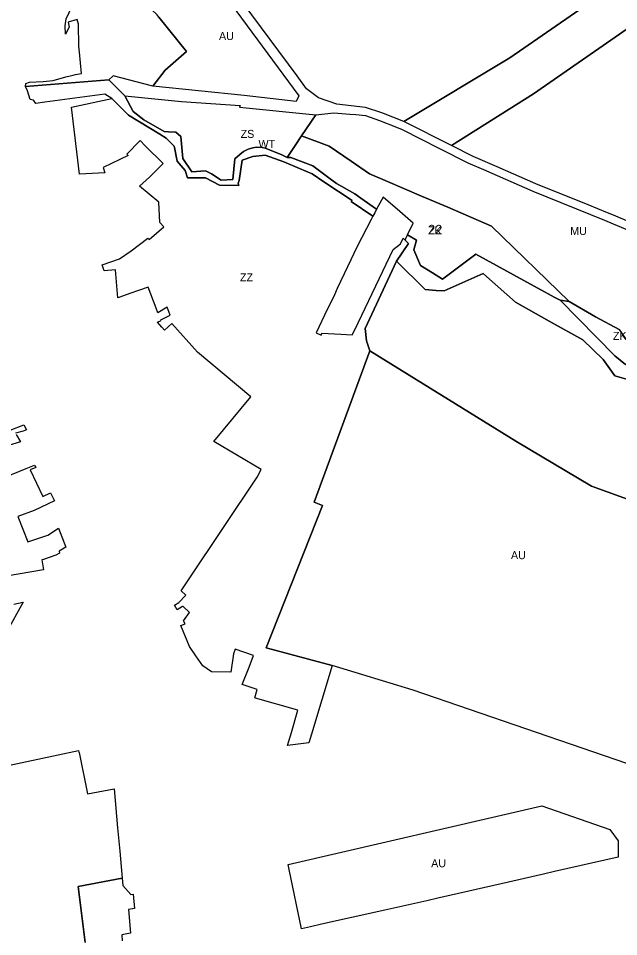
# Model space of a CAD drawing. Extents: x -522079 to -518833, y -1142398 to -1139961.
# Drawn here: x -520390 to -520015, y -1141329 to -1140756 of the extents above; entities that cross this region are included whole.
import ezdxf

# ---------------------------------------------------------------- set-up
doc = ezdxf.new("R2010")
doc.units = 0
for name, color, linetype in [('90640013', 7, 'Continuous'), ('90660013', 7, 'Continuous'), ('90670013', 7, 'Continuous'), ('90710013', 7, 'Continuous'), ('90710023', 7, 'Continuous'), ('90750013', 7, 'Continuous'), ('90830013', 7, 'Continuous'), ('ID_navrh', 7, 'Continuous')]:
    doc.layers.add(name, color=color, linetype=linetype)

msp = doc.modelspace()

# ---------------------------------------------------------------- linework, layer by layer
at = {"layer": '90640013'}
msp.add_lwpolyline([(-520333.88, -1140793.93), (-520323.97, -1140803.87), (-520318.65, -1140813.75), (-520312.05, -1140818.87), (-520299.28, -1140826.27), (-520296.51, -1140826.43), (-520292.1, -1140826.69), (-520288.8, -1140829.33), (-520287.73, -1140843.06), (-520282.03, -1140851.48), (-520273.45, -1140850.74), (-520269.7, -1140852.75), (-520263.6, -1140856.56), (-520256.4, -1140856.26), (-520255.19, -1140843.37), (-520252.14, -1140840.56), (-520249.76, -1140838.76), (-520246.91, -1140837.31), (-520243.86, -1140836.42), (-520241.55, -1140836.1), (-520237.99, -1140836.24), (-520236.14, -1140836.59), (-520226.15, -1140840.68), (-520222.55, -1140842.43), (-520220.12, -1140842.45), (-520206.43, -1140847.59), (-520196.46, -1140855.08), (-520191.59, -1140858.73), (-520180.27, -1140865.22), (-520176.48, -1140867.88), (-520166.62, -1140874.78), (-520167.79, -1140876.9), (-520168.95, -1140879.03), (-520182.55, -1140869.96), (-520181.95, -1140869.32), (-520199.46, -1140857.65), (-520206.95, -1140852.59), (-520214.8, -1140849.22), (-520224.47, -1140845.06), (-520236.26, -1140840.92), (-520243.98, -1140841.86), (-520250.57, -1140844.07), (-520252.48, -1140856.73), (-520253.04, -1140858.58), (-520252.57, -1140859.91), (-520264.75, -1140859.75), (-520273.49, -1140855.19), (-520284.67, -1140855.24), (-520286.12, -1140850.49), (-520291.11, -1140844.75), (-520292.87, -1140836.23), (-520293.05, -1140835.38), (-520298.02, -1140830.46), (-520302.1, -1140827.97), (-520321.54, -1140816.1), (-520332, -1140805.6), (-520331.98, -1140805.6), (-520336.41, -1140802.99), (-520373.88, -1140807.82), (-520379.43, -1140808.81), (-520380.85, -1140806.63), (-520383.09, -1140806.25), (-520384.61, -1140800.83), (-520385.85, -1140798.14)], close=True, dxfattribs=at)
msp.add_lwpolyline([(-520003.11, -1140982.94), (-520017.73, -1140978.78), (-520025.01, -1140968.52), (-520037.81, -1140956.24), (-520058.84, -1140944.58), (-520079.83, -1140932.73), (-520097.88, -1140916.76), (-520100.12, -1140914.78), (-520124.49, -1140925.8), (-520129.31, -1140925.55), (-520136.24, -1140924.81), (-520154.18, -1140907.23), (-520146.75, -1140896.12), (-520148.74, -1140894), (-520148.27, -1140892.97), (-520147.23, -1140890.72), (-520141.61, -1140894.1), (-520143.26, -1140900.05), (-520139.09, -1140909.85), (-520131.65, -1140914.52), (-520125.39, -1140918.45), (-520104.55, -1140902.75), (-520061.67, -1140926.36), (-520059.41, -1140927.64), (-520055.67, -1140929.56), (-520051.93, -1140931.48), (-520017.69, -1140966.19), (-520011.16, -1140971.75)], dxfattribs=at)
at = {"layer": '90660013'}
msp.add_lwpolyline([(-520213.5, -1140828.96), (-520217.49, -1140834.9), (-520222.55, -1140842.43), (-520226.15, -1140840.68), (-520236.14, -1140836.59), (-520237.99, -1140836.24), (-520241.55, -1140836.1), (-520243.86, -1140836.42), (-520246.91, -1140837.31), (-520249.76, -1140838.76), (-520252.14, -1140840.56), (-520255.19, -1140843.37), (-520256.4, -1140856.26), (-520263.6, -1140856.56), (-520269.7, -1140852.75), (-520273.45, -1140850.74), (-520282.03, -1140851.48), (-520287.73, -1140843.06), (-520288.8, -1140829.33), (-520292.1, -1140826.69), (-520296.51, -1140826.43), (-520299.28, -1140826.27), (-520312.05, -1140818.87), (-520318.65, -1140813.75), (-520323.97, -1140803.87), (-520288.38, -1140807.41), (-520251.92, -1140810), (-520252.34, -1140811), (-520204.62, -1140815.75)], close=True, dxfattribs=at)
at = {"layer": '90670013'}
for points in [[(-520302.54, -1140754.92), (-520285.25, -1140776.21), (-520298.77, -1140787.91), (-520306.3, -1140797.86), (-520331.09, -1140791.46), (-520333.88, -1140793.93), (-520385.85, -1140798.14), (-520385.62, -1140796.31), (-520383.53, -1140795.4), (-520374.96, -1140794.94), (-520368.73, -1140794.29), (-520360.72, -1140792.17), (-520356.2, -1140791.03), (-520354.62, -1140790.65), (-520350.89, -1140789.92), (-520352.17, -1140776.77), (-520352.71, -1140773.02), (-520352.78, -1140759.2), (-520353.64, -1140756.21), (-520359.31, -1140757.88), (-520358.59, -1140760.98), (-520361.04, -1140765.41), (-520361.11, -1140760.14), (-520360.42, -1140755.8), (-520354.98, -1140743.86)], [(-520395.43, -1141012.8), (-520386.94, -1141009.33), (-520385.38, -1141012.44), (-520387.31, -1141013.36), (-520392.22, -1141014.66)], [(-520391.74, -1141015.46), (-520389.08, -1141019.93), (-520401.32, -1141023.68)], [(-520399.24, -1141042.3), (-520385.48, -1141036.63), (-520380.26, -1141034.58), (-520380, -1141035.01), (-520379.56, -1141036.01), (-520382.96, -1141037.48), (-520375, -1141054.13), (-520370.31, -1141051.82), (-520367.77, -1141056.92), (-520380.42, -1141062.83), (-520390.79, -1141066.51), (-520384.48, -1141082.4), (-520371.97, -1141078.27), (-520365.3, -1141073.88), (-520360.71, -1141085.77), (-520364.98, -1141088.31), (-520364.74, -1141089.55), (-520366.94, -1141090.81), (-520374.62, -1141093.47), (-520375.66, -1141093.7), (-520374.68, -1141099.98), (-520397.79, -1141103.97)], [(-520393.3, -1141121.36), (-520387.46, -1141120.02), (-520397.97, -1141139.24)], [(-520348.74, -1141332.58), (-520353.1, -1141297.63), (-520325.5, -1141292.44), (-520325.09, -1141296.95), (-520320.11, -1141302.71), (-520318.74, -1141302.49), (-520317.9, -1141311.37), (-520321.67, -1141312.05), (-520320.3, -1141326.77), (-520325.78, -1141327.89), (-520325.53, -1141331.62)]]:
    msp.add_lwpolyline(points, dxfattribs=at)
msp.add_lwpolyline([(-520209, -1141207.86), (-520222.29, -1141209.66), (-520219.73, -1141201.41), (-520215.84, -1141187.57), (-520242.23, -1141179.94), (-520242.77, -1141179.78), (-520241.26, -1141174.54), (-520250.48, -1141171.53), (-520246.26, -1141160.66), (-520243.41, -1141153.37), (-520254.95, -1141149.39), (-520256.03, -1141152.27), (-520257.71, -1141163.82), (-520269.77, -1141163.56), (-520275.19, -1141159.91), (-520279.46, -1141153.62), (-520283.41, -1141147.79), (-520288.84, -1141134.57), (-520286.17, -1141133.59), (-520287.28, -1141131.69), (-520283.49, -1141126.48), (-520287.59, -1141122.55), (-520287.92, -1141122.9), (-520291.23, -1141124.89), (-520292.95, -1141121.95), (-520290.1, -1141120.29), (-520285.76, -1141115.8), (-520288.75, -1141112.92), (-520283.75, -1141105.56), (-520241.17, -1141042.05), (-520238.67, -1141037.33), (-520268.23, -1141019.69), (-520245.17, -1140991.88), (-520278.46, -1140964.1), (-520294.61, -1140946.2), (-520299.04, -1140950.24), (-520300.74, -1140948.36), (-520303.52, -1140945.28), (-520301.23, -1140944.23), (-520301.37, -1140943.86), (-520295.5, -1140940.8), (-520297.35, -1140935.94), (-520303.17, -1140939.4), (-520304.25, -1140936.55), (-520309.29, -1140923.33), (-520320.68, -1140927.43), (-520327.1, -1140929.75), (-520328.35, -1140930.16), (-520329.64, -1140912.5), (-520336.89, -1140913.16), (-520338.02, -1140909.41), (-520327.22, -1140905.73), (-520319.94, -1140900.63), (-520309.51, -1140892.73), (-520308.71, -1140893.63), (-520299.57, -1140885.75), (-520301.99, -1140882.96), (-520302.58, -1140870.36), (-520314.68, -1140860.36), (-520308.39, -1140854.65), (-520299.93, -1140846.14), (-520311.07, -1140835.07), (-520314.26, -1140831.9), (-520322.72, -1140840.41), (-520321.89, -1140841.23), (-520337.42, -1140848.62), (-520336.35, -1140852.04), (-520352.17, -1140852.78), (-520357.19, -1140810.98), (-520332, -1140805.6), (-520321.54, -1140816.1), (-520302.1, -1140827.97), (-520298.02, -1140830.46), (-520293.05, -1140835.38), (-520292.87, -1140836.23), (-520291.11, -1140844.75), (-520286.12, -1140850.49), (-520284.67, -1140855.24), (-520273.49, -1140855.19), (-520264.75, -1140859.75), (-520252.57, -1140859.91), (-520253.04, -1140858.58), (-520252.48, -1140856.73), (-520250.57, -1140844.07), (-520243.98, -1140841.86), (-520236.26, -1140840.92), (-520224.47, -1140845.06), (-520214.8, -1140849.22), (-520206.95, -1140852.59), (-520199.46, -1140857.65), (-520181.95, -1140869.32), (-520182.55, -1140869.96), (-520168.95, -1140879.03), (-520170.08, -1140881.1), (-520178.74, -1140898.05), (-520184.7, -1140910.65), (-520191.17, -1140924.29), (-520193, -1140928.16), (-520196.08, -1140934.67), (-520197.39, -1140937.44), (-520204.29, -1140951.99), (-520201.3, -1140953.32), (-520201.27, -1140953.32), (-520200.79, -1140952.24), (-520189.01, -1140952.86), (-520181.77, -1140953.24), (-520180.26, -1140950.09), (-520156.19, -1140899.86), (-520151.68, -1140896.26), (-520149.94, -1140892.73), (-520148.74, -1140894), (-520146.75, -1140896.12), (-520154.18, -1140907.23), (-520173.77, -1140949.3), (-520172.97, -1140956.99), (-520170.88, -1140963.13), (-520205.51, -1141057.7), (-520200.4, -1141059.73), (-520235.62, -1141148.58), (-520194.38, -1141159.65), (-520207.36, -1141202.47)], close=True, dxfattribs=at)
at = {"layer": '90710013'}
msp.add_lwpolyline([(-520010.06, -1140762.16), (-520068.52, -1140802.68), (-520119.77, -1140834.99), (-520149.6, -1140820.02), (-520083.41, -1140780.15), (-520025.44, -1140739.97)], dxfattribs=at)
msp.add_lwpolyline([(-520015.17, -1140949.95), (-520009.84, -1140957.29), (-520002.28, -1140962.91), (-519999.3, -1140964.63), (-519986.94, -1140971.3), (-519974.08, -1140974.02), (-519965.47, -1140973.69), (-519979.37, -1140981.19), (-520011.16, -1140971.75), (-520017.69, -1140966.19), (-520051.93, -1140931.48), (-520046.33, -1140932.29), (-520029.76, -1140941.98)], close=True, dxfattribs=at)
at = {"layer": '90710023'}
msp.add_lwpolyline([(-520213.5, -1140828.96), (-520196.23, -1140835.45), (-520182.58, -1140844.72), (-520170.98, -1140852.6), (-520159.88, -1140857.36), (-520138.6, -1140866.49), (-520122.13, -1140873.55), (-520094.9, -1140885.23), (-520046.33, -1140932.29), (-520051.93, -1140931.48), (-520055.67, -1140929.56), (-520059.41, -1140927.64), (-520061.67, -1140926.36), (-520104.55, -1140902.75), (-520125.39, -1140918.45), (-520131.65, -1140914.52), (-520139.09, -1140909.85), (-520143.26, -1140900.05), (-520141.61, -1140894.1), (-520147.23, -1140890.72), (-520143.83, -1140883.35), (-520152.09, -1140876.15), (-520162.5, -1140867.24), (-520166.62, -1140874.78), (-520176.48, -1140867.88), (-520180.27, -1140865.22), (-520191.59, -1140858.73), (-520196.46, -1140855.08), (-520206.43, -1140847.59), (-520220.12, -1140842.45), (-520222.55, -1140842.43), (-520217.49, -1140834.9)], close=True, dxfattribs=at)
at = {"layer": '90750013'}
for points in [[(-520306.3, -1140797.86), (-520298.77, -1140787.91), (-520285.25, -1140776.21), (-520302.54, -1140754.92), (-520303.74, -1140753.44), (-520314.83, -1140742.62), (-520298.98, -1140728.74), (-520284.03, -1140723.41), (-520276.72, -1140720.19), (-520215.27, -1140803.99), (-520216.9, -1140807.42), (-520249.32, -1140803.75)], [(-520194.38, -1141159.65), (-520235.62, -1141148.58), (-520200.4, -1141059.73), (-520205.51, -1141057.7), (-520170.88, -1140963.13), (-520079.53, -1141019.58), (-520032.33, -1141047.7), (-519951.21, -1141077.01), (-519948.1, -1141084.44), (-519980.55, -1141165.39), (-520002.99, -1141223.35), (-520143.75, -1141175.06)], [(-520128.28, -1141304.98), (-520135.15, -1141306.52), (-520161.5, -1141312.42), (-520200.99, -1141321.26), (-520207.86, -1141322.8), (-520213.54, -1141324.07), (-520221.2, -1141287.03), (-520221.83, -1141283.92), (-520063.43, -1141247.22), (-520020.82, -1141261.97), (-520015.63, -1141269.2), (-520015.8, -1141279.3), (-520055.42, -1141288.36), (-520062.28, -1141289.92), (-520088.69, -1141295.96), (-520120.09, -1141303.14)]]:
    msp.add_lwpolyline(points, close=True, dxfattribs=at)
for points in [[(-520025.44, -1140739.97), (-520083.41, -1140780.15), (-520149.6, -1140820.02), (-520163.23, -1140814.61), (-520173.51, -1140811.18), (-520191.48, -1140809.25), (-520202.97, -1140805.12), (-520210.31, -1140799.64), (-520216.26, -1140791.5), (-520249.86, -1140745.99)], [(-519997.49, -1140887.4), (-520018.57, -1140878.52), (-520022.3, -1140876.95), (-520034.41, -1140872.06), (-520067.09, -1140858.86), (-520091.34, -1140848.28), (-520106.23, -1140841.79), (-520119.77, -1140834.99), (-520068.52, -1140802.68), (-520010.06, -1140762.16)], [(-520400.61, -1141222.82), (-520352.78, -1141212.63), (-520352.51, -1141213.97), (-520352.46, -1141213.96), (-520347.19, -1141239.81), (-520330.62, -1141236.74), (-520328.39, -1141261.02), (-520327.05, -1141275.53), (-520325.5, -1141292.44), (-520353.1, -1141297.63), (-520348.74, -1141332.58)]]:
    msp.add_lwpolyline(points, dxfattribs=at)
at = {"layer": '90830013'}
for points in [[(-520015.17, -1140949.95), (-520029.76, -1140941.98), (-520046.33, -1140932.29), (-520094.9, -1140885.23), (-520122.13, -1140873.55), (-520138.6, -1140866.49), (-520159.88, -1140857.36), (-520170.98, -1140852.6), (-520182.58, -1140844.72), (-520196.23, -1140835.45), (-520213.5, -1140828.96), (-520204.62, -1140815.75), (-520193.39, -1140814.61), (-520183.32, -1140815.4), (-520179.62, -1140815.67), (-520173.51, -1140816.17), (-520164.79, -1140819.27), (-520154.23, -1140823.56), (-520150.53, -1140825.07), (-520127.38, -1140836.75), (-520109.6, -1140845.72), (-520099.84, -1140850.03), (-520069.02, -1140863.47), (-520024.21, -1140881.57), (-520022.73, -1140882.19), (-519999.48, -1140892)], [(-519951.21, -1141077.01), (-520032.33, -1141047.7), (-520079.53, -1141019.58), (-520170.88, -1140963.13), (-520172.97, -1140956.99), (-520173.77, -1140949.3), (-520154.18, -1140907.23), (-520136.24, -1140924.81), (-520129.31, -1140925.55), (-520124.49, -1140925.8), (-520100.12, -1140914.78), (-520097.88, -1140916.76), (-520079.83, -1140932.73), (-520058.84, -1140944.58), (-520037.81, -1140956.24), (-520025.01, -1140968.52), (-520017.73, -1140978.78), (-520003.11, -1140982.94)]]:
    msp.add_lwpolyline(points, dxfattribs=at)

# ---------------------------------------------------------------- texts
at = {"layer": '90640013'}
msp.add_text('WT', height=5, rotation=0, dxfattribs=at).set_placement((-520240.394, -1140836.48))
at = {"layer": '90660013'}
msp.add_text('ZS', height=5, rotation=360, dxfattribs=at).set_placement((-520251.537, -1140830.215))
at = {"layer": '90670013'}
msp.add_text('ZZ', height=5, rotation=0, dxfattribs=at).set_placement((-520251.97, -1140919.778))
at = {"layer": '90710013'}
msp.add_text('ZK', height=5, rotation=360, dxfattribs=at).set_placement((-520018.973, -1140956.335))
at = {"layer": '90710023'}
msp.add_text('ZK', height=5, rotation=360, dxfattribs=at).set_placement((-520134.44, -1140890.521))
at = {"layer": '90750013'}
msp.add_text('AU', height=5, dxfattribs=at).set_placement((-520265.05, -1140769.114))
for rotation, p in [(0, (-520082.655, -1141093.24)), (360, (-520132.514, -1141285.645))]:
    msp.add_text('AU', height=5, rotation=rotation, dxfattribs=at).set_placement(p)
at = {"layer": '90830013'}
msp.add_text('MU', height=5, rotation=0, dxfattribs=at).set_placement((-520045.661, -1140890.845))
at = {"layer": 'ID_navrh'}
msp.add_text('22', height=6, rotation=360, dxfattribs=at).set_placement((-520134.44, -1140890.521))

doc.saveas('drawing.dxf')
